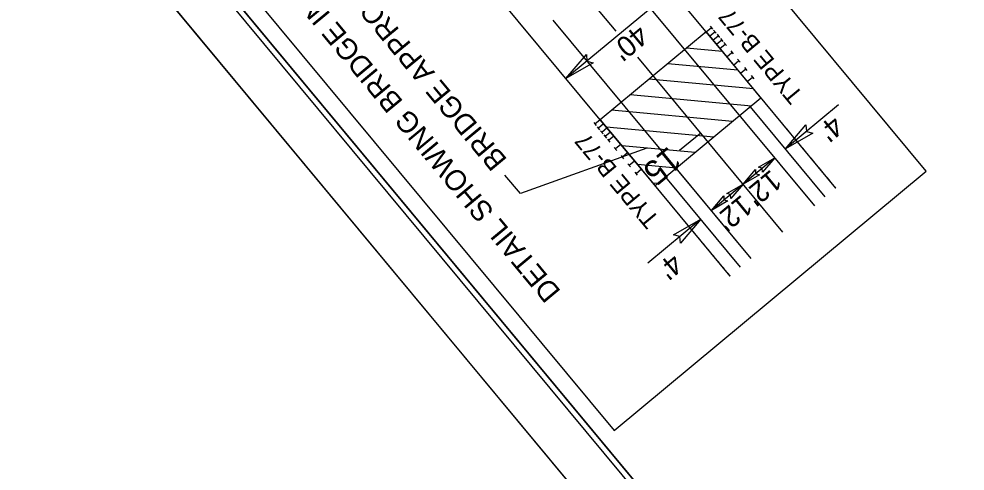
# Model space of a CAD drawing. Extents: x 2597026 to 2598995, y 852197 to 854192.
# Drawn here: x 2597490.1 to 2597902.9, y 852711.2 to 852908.6 of the extents above; entities that cross this region are included whole.
import ezdxf

# ---------------------------------------------------------------- set-up
doc = ezdxf.new("R2010")
doc.units = 0
for name, color, linetype in [('Old_Level_1', 7, 'Continuous'), ('Old_Level_2', 7, 'Continuous'), ('Prop Approach Slab', 7, 'Continuous'), ('Prop Dimension', 7, 'Continuous'), ('Prop Dimension Text', 7, 'Continuous'), ('Prop EOT', 7, 'Continuous'), ('Prop Guardrail', 7, 'Continuous'), ('Prop Horizontal Alignment', 7, 'Continuous'), ('Prop Horizontal Alignment Tick Label', 7, 'Continuous'), ('Prop Horizontal Alignment Tick Large', 7, 'Continuous'), ('Prop Paved Shoulder', 7, 'Continuous'), ('Prop Roadway Bridge', 7, 'Continuous'), ('Prop Structure Anchor Unit CELL', 7, 'Continuous'), ('Prop Terminator CELL', 7, 'Continuous'), ('Sheet Clip Boundary CELL', 7, 'Continuous'), ('Sheet Cutting Line CELL', 7, 'Continuous'), ('Sheet Plan CELL', 7, 'Continuous'), ('Sheet Plan Layout CELL', 7, 'Continuous'), ('Sheet Plot Border Inside CELL', 7, 'Continuous'), ('Sheet Plot Border Outside CELL', 7, 'Continuous')]:
    doc.layers.add(name, color=color, linetype=linetype)

msp = doc.modelspace()

# ---------------------------------------------------------------- linework, layer by layer
at = {"layer": 'Old_Level_1'}
for p, q in [((2597507.53, 853020.63), (2597749.73, 852728.97)), ((2597763.98, 852852.17), (2597708.85, 852832.31)), ((2597749.73, 852728.97), (2597885.92, 852842.07)), ((2597708.85, 852832.31), (2597702.12, 852840.42))]:
    msp.add_line(p, q, dxfattribs=at)
msp.add_lwpolyline([(2597885.92, 852842.07), (2597643.72, 853133.73), (2597507.53, 853020.63)], dxfattribs=at)
at = {"layer": 'Old_Level_2'}
for p, q in [((2597846.51, 852834.7), (2597807.87, 852881.24)), ((2597800.33, 852796.35), (2597761.65, 852842.92))]:
    msp.add_line(p, q, dxfattribs=at)
at = {"layer": 'Prop Approach Slab'}
for p, q in [((2597789.88, 852902.87), (2597813.82, 852874)), ((2597796.98, 852894.31), (2597781.31, 852895.76)), ((2597803.75, 852886.15), (2597773.14, 852888.98)), ((2597810.51, 852877.99), (2597764.97, 852882.21)), ((2597809.64, 852870.54), (2597756.79, 852875.43)), ((2597813.82, 852874), (2597767.63, 852835.7)), ((2597801.47, 852863.76), (2597748.62, 852868.66)), ((2597743.69, 852864.57), (2597767.63, 852835.7)), ((2597793.3, 852856.99), (2597746.38, 852861.34)), ((2597785.13, 852850.21), (2597753.14, 852853.18)), ((2597776.96, 852843.44), (2597759.91, 852845.02)), ((2597768.79, 852836.66), (2597766.67, 852836.86))]:
    msp.add_line(p, q, dxfattribs=at)
at = {"layer": 'Prop Dimension'}
for p, q in [((2597774.92, 852920.89), (2597728.76, 852882.56)), ((2597847.6, 852871.01), (2597824.52, 852851.84)), ((2597819.83, 852847.94), (2597806.02, 852836.48)), ((2597806.02, 852836.48), (2597792.21, 852825.01)), ((2597787.6, 852821.18), (2597764.52, 852802.01))]:
    msp.add_line(p, q, dxfattribs=at)
at = {"layer": 'Prop EOT'}
for p, q in [((2597837.27, 852827.03), (2597751.13, 852930.75)), ((2597809.57, 852804.03), (2597723.22, 852908.01)), ((2597809.57, 852804.03), (2597776.89, 852843.39))]:
    msp.add_line(p, q, dxfattribs=at)
at = {"layer": 'Prop Guardrail'}
for p, q in [((2597807.87, 852881.25), (2597789.88, 852902.87)), ((2597761.68, 852842.95), (2597743.69, 852864.57))]:
    msp.add_line(p, q, dxfattribs=at)
for points in [[(2597846.51, 852834.7), (2597846.38, 852834.86), (2597846.25, 852835.03), (2597846.11, 852835.19), (2597845.81, 852835.55), (2597845.5, 852835.92), (2597845.2, 852836.28), (2597844.9, 852836.65), (2597844.59, 852837.01), (2597844.29, 852837.38), (2597843.99, 852837.75), (2597843.68, 852838.11), (2597843.38, 852838.48), (2597843.08, 852838.84), (2597842.77, 852839.21), (2597842.47, 852839.57), (2597842.17, 852839.94), (2597841.86, 852840.3), (2597841.56, 852840.67), (2597841.26, 852841.03), (2597840.95, 852841.4), (2597840.65, 852841.77), (2597840.34, 852842.13), (2597840.04, 852842.5), (2597839.74, 852842.86), (2597839.43, 852843.23), (2597839.13, 852843.59), (2597838.83, 852843.96), (2597838.52, 852844.32), (2597838.22, 852844.69), (2597837.92, 852845.06), (2597837.61, 852845.42), (2597837.31, 852845.79), (2597837.01, 852846.15), (2597836.7, 852846.52), (2597836.4, 852846.88), (2597836.1, 852847.25), (2597835.79, 852847.61), (2597835.49, 852847.98), (2597835.19, 852848.35), (2597834.88, 852848.71), (2597834.58, 852849.08), (2597834.28, 852849.44), (2597833.97, 852849.81), (2597833.67, 852850.17), (2597833.36, 852850.54), (2597833.06, 852850.9), (2597832.76, 852851.27), (2597832.45, 852851.63), (2597832.15, 852852), (2597831.85, 852852.37), (2597831.54, 852852.73), (2597831.24, 852853.1), (2597830.94, 852853.46), (2597830.63, 852853.83), (2597830.33, 852854.19), (2597830.03, 852854.56), (2597829.72, 852854.92), (2597829.42, 852855.29), (2597829.12, 852855.66), (2597828.81, 852856.02), (2597828.51, 852856.39), (2597828.21, 852856.75), (2597827.9, 852857.12), (2597827.6, 852857.48), (2597827.29, 852857.85), (2597826.99, 852858.21), (2597826.69, 852858.58), (2597826.38, 852858.94), (2597826.08, 852859.31), (2597825.78, 852859.68), (2597825.47, 852860.04), (2597825.17, 852860.41), (2597824.87, 852860.77), (2597824.56, 852861.14), (2597824.26, 852861.5), (2597823.96, 852861.87), (2597823.65, 852862.23), (2597823.35, 852862.6), (2597823.05, 852862.97), (2597822.74, 852863.33), (2597822.44, 852863.7), (2597822.14, 852864.06), (2597821.83, 852864.43), (2597821.53, 852864.79), (2597821.22, 852865.16), (2597820.92, 852865.52), (2597820.62, 852865.89), (2597820.31, 852866.26), (2597820.01, 852866.62), (2597819.71, 852866.99), (2597819.4, 852867.35), (2597819.1, 852867.72), (2597818.8, 852868.08), (2597818.49, 852868.45), (2597818.19, 852868.81), (2597817.89, 852869.18), (2597817.58, 852869.54), (2597817.28, 852869.91), (2597816.98, 852870.28), (2597816.67, 852870.64), (2597816.37, 852871.01), (2597816.07, 852871.37), (2597815.76, 852871.74), (2597815.46, 852872.1), (2597815.16, 852872.47), (2597814.85, 852872.83), (2597814.55, 852873.2), (2597814.24, 852873.57), (2597813.94, 852873.93), (2597813.64, 852874.3), (2597813.33, 852874.66), (2597813.03, 852875.03), (2597812.73, 852875.39), (2597812.42, 852875.76), (2597812.12, 852876.12), (2597811.82, 852876.49), (2597811.51, 852876.85), (2597811.21, 852877.22), (2597810.91, 852877.59), (2597810.6, 852877.95), (2597810.3, 852878.32), (2597810, 852878.68), (2597809.69, 852879.05), (2597809.39, 852879.41), (2597809.09, 852879.78), (2597808.78, 852880.14), (2597808.48, 852880.51), (2597808.17, 852880.88), (2597807.87, 852881.24)], [(2597761.65, 852842.92), (2597761.91, 852842.61), (2597762.16, 852842.3), (2597762.42, 852841.99), (2597762.68, 852841.68), (2597762.93, 852841.37), (2597763.19, 852841.06), (2597763.44, 852840.76), (2597763.7, 852840.45), (2597763.96, 852840.14), (2597764.21, 852839.83), (2597764.47, 852839.52), (2597764.73, 852839.21), (2597764.98, 852838.9), (2597765.24, 852838.6), (2597765.49, 852838.29), (2597765.75, 852837.98), (2597766.01, 852837.67), (2597766.26, 852837.36), (2597766.52, 852837.05), (2597766.78, 852836.74), (2597767.03, 852836.44), (2597767.29, 852836.13), (2597767.55, 852835.82), (2597767.8, 852835.51), (2597768.06, 852835.2), (2597768.31, 852834.89), (2597768.57, 852834.58), (2597768.83, 852834.28), (2597769.08, 852833.97), (2597769.34, 852833.66), (2597769.6, 852833.35), (2597769.85, 852833.04), (2597770.11, 852832.73), (2597770.37, 852832.42), (2597770.62, 852832.12), (2597770.88, 852831.81), (2597771.13, 852831.5), (2597771.39, 852831.19), (2597771.65, 852830.88), (2597771.9, 852830.57), (2597772.16, 852830.26), (2597772.42, 852829.95), (2597772.67, 852829.65), (2597772.93, 852829.34), (2597773.18, 852829.03), (2597773.44, 852828.72), (2597773.7, 852828.41), (2597773.95, 852828.1), (2597774.21, 852827.79), (2597774.47, 852827.49), (2597774.72, 852827.18), (2597774.98, 852826.87), (2597775.24, 852826.56), (2597775.49, 852826.25), (2597775.75, 852825.94), (2597776, 852825.63), (2597776.26, 852825.33), (2597776.52, 852825.02), (2597776.77, 852824.71), (2597777.03, 852824.4), (2597777.29, 852824.09), (2597777.54, 852823.78), (2597777.8, 852823.47), (2597778.06, 852823.17), (2597778.31, 852822.86), (2597778.57, 852822.55), (2597778.82, 852822.24), (2597779.08, 852821.93), (2597779.34, 852821.62), (2597779.59, 852821.31), (2597779.85, 852821.01), (2597780.11, 852820.7), (2597780.36, 852820.39), (2597780.62, 852820.08), (2597780.87, 852819.77), (2597781.13, 852819.46), (2597781.39, 852819.15), (2597781.64, 852818.85), (2597781.9, 852818.54), (2597782.16, 852818.23), (2597782.41, 852817.92), (2597782.67, 852817.61), (2597782.93, 852817.3), (2597783.18, 852816.99), (2597783.44, 852816.68), (2597783.69, 852816.38), (2597783.95, 852816.07), (2597784.21, 852815.76), (2597784.46, 852815.45), (2597784.72, 852815.14), (2597784.98, 852814.83), (2597785.23, 852814.52), (2597785.49, 852814.22), (2597785.75, 852813.91), (2597786, 852813.6), (2597786.26, 852813.29), (2597786.51, 852812.98), (2597786.77, 852812.67), (2597787.03, 852812.36), (2597787.28, 852812.06), (2597787.54, 852811.75), (2597787.8, 852811.44), (2597788.05, 852811.13), (2597788.31, 852810.82), (2597788.57, 852810.51), (2597788.82, 852810.2), (2597789.08, 852809.9), (2597789.33, 852809.59), (2597789.59, 852809.28), (2597789.85, 852808.97), (2597790.1, 852808.66), (2597790.36, 852808.35), (2597790.62, 852808.04), (2597790.87, 852807.74), (2597791.13, 852807.43), (2597791.38, 852807.12), (2597791.64, 852806.81), (2597791.9, 852806.5), (2597792.15, 852806.19), (2597792.41, 852805.88), (2597792.67, 852805.57), (2597792.92, 852805.27), (2597793.18, 852804.96), (2597793.44, 852804.65), (2597793.69, 852804.34), (2597793.95, 852804.03), (2597794.2, 852803.72), (2597794.46, 852803.41), (2597794.72, 852803.11), (2597794.97, 852802.8), (2597795.23, 852802.49), (2597795.49, 852802.18), (2597795.74, 852801.87), (2597796, 852801.56), (2597796.26, 852801.25), (2597796.51, 852800.95), (2597796.77, 852800.64), (2597797.02, 852800.33), (2597797.28, 852800.02), (2597797.54, 852799.71), (2597797.79, 852799.4), (2597798.05, 852799.09), (2597798.31, 852798.79), (2597798.56, 852798.48), (2597798.82, 852798.17), (2597799.07, 852797.86), (2597799.33, 852797.55), (2597799.59, 852797.24), (2597799.84, 852796.93), (2597800.1, 852796.63), (2597800.18, 852796.53), (2597800.25, 852796.44), (2597800.33, 852796.35)]]:
    msp.add_open_spline(points, degree=3, dxfattribs=at)
at = {"layer": 'Prop Horizontal Alignment'}
for p, q in [((2597750.61, 852903.2), (2597702.87, 852960.69)), ((2597823.42, 852815.53), (2597760.03, 852891.86))]:
    msp.add_line(p, q, dxfattribs=at)
at = {"layer": 'Prop Horizontal Alignment Tick Large'}
msp.add_line((2597787.53, 852858.75), (2597778.29, 852851.08), dxfattribs=at)
at = {"layer": 'Prop Paved Shoulder'}
for p, q in [((2597841.88, 852830.86), (2597809.22, 852870.19)), ((2597804.95, 852800.19), (2597772.27, 852839.55))]:
    msp.add_line(p, q, dxfattribs=at)
at = {"layer": 'Prop Roadway Bridge'}
for p, q in [((2597789.88, 852902.87), (2597703.64, 853006.73)), ((2597743.69, 852864.57), (2597657.45, 852968.43)), ((2597789.88, 852902.87), (2597743.69, 852864.57)), ((2597790.22, 852902.47), (2597789.48, 852902.54))]:
    msp.add_line(p, q, dxfattribs=at)
at = {"layer": 'Prop Structure Anchor Unit CELL'}
for p, q in [((2597789.88, 852902.87), (2597792.19, 852904.78)), ((2597789.88, 852902.87), (2597807.83, 852881.22)), ((2597791.38, 852901.06), (2597793.69, 852902.98)), ((2597791.64, 852905.45), (2597792.74, 852904.12)), ((2597793.14, 852903.64), (2597794.24, 852902.32)), ((2597792.87, 852899.26), (2597795.18, 852901.18)), ((2597794.37, 852897.46), (2597796.68, 852899.37)), ((2597794.64, 852901.84), (2597795.73, 852900.51)), ((2597796.13, 852900.03), (2597797.23, 852898.71)), ((2597797.63, 852898.23), (2597798.72, 852896.91)), ((2597795.87, 852895.65), (2597798.18, 852897.57)), ((2597800.62, 852894.62), (2597801.72, 852893.3)), ((2597798.86, 852892.04), (2597801.17, 852893.96)), ((2597801.85, 852888.43), (2597804.16, 852890.35)), ((2597803.61, 852891.01), (2597804.71, 852889.69)), ((2597804.84, 852884.83), (2597807.15, 852886.74)), ((2597806.6, 852887.4), (2597807.7, 852886.08)), ((2597807.83, 852881.22), (2597810.14, 852883.13)), ((2597809.6, 852883.79), (2597810.69, 852882.47)), ((2597740.84, 852863.32), (2597741.93, 852862)), ((2597743.69, 852864.57), (2597741.38, 852862.66)), ((2597742.33, 852861.52), (2597743.43, 852860.19)), ((2597745.19, 852862.77), (2597742.88, 852860.85)), ((2597743.69, 852864.57), (2597761.65, 852842.92)), ((2597743.83, 852859.71), (2597744.92, 852858.39)), ((2597746.69, 852860.96), (2597744.38, 852859.05)), ((2597745.32, 852857.91), (2597746.42, 852856.58)), ((2597748.18, 852859.16), (2597745.87, 852857.25)), ((2597749.68, 852857.36), (2597747.37, 852855.44)), ((2597746.82, 852856.1), (2597747.92, 852854.78)), ((2597752.67, 852853.75), (2597750.36, 852851.83)), ((2597749.81, 852852.49), (2597750.91, 852851.17)), ((2597752.8, 852848.89), (2597753.9, 852847.56)), ((2597755.66, 852850.14), (2597753.35, 852848.22)), ((2597755.8, 852845.28), (2597756.89, 852843.95)), ((2597758.65, 852846.53), (2597756.34, 852844.62)), ((2597758.79, 852841.67), (2597759.88, 852840.35)), ((2597761.65, 852842.92), (2597759.34, 852841.01))]:
    msp.add_line(p, q, dxfattribs=at)
at = {"layer": 'Prop Terminator CELL'}
for points in [[(2597740.63, 852889.39), (2597728.76, 852882.56), (2597737.67, 852893.08), (2597737.88, 852890.13)], [(2597836.39, 852858.68), (2597824.52, 852851.84), (2597833.43, 852862.36), (2597833.64, 852859.41)], [(2597812.75, 852843.88), (2597819.88, 852847.98), (2597814.53, 852841.67), (2597814.41, 852843.44)], [(2597813.14, 852840.58), (2597806.02, 852836.48), (2597811.37, 852842.79), (2597811.49, 852841.02)], [(2597798.9, 852832.38), (2597806.02, 852836.48), (2597800.67, 852830.17), (2597800.55, 852831.93)], [(2597799.33, 852829.11), (2597792.21, 852825.01), (2597797.56, 852831.32), (2597797.68, 852829.55)], [(2597775.72, 852814.34), (2597787.6, 852821.18), (2597778.68, 852810.66), (2597778.48, 852813.61)]]:
    msp.add_lwpolyline(points, close=True, dxfattribs=at)
at = {"layer": 'Sheet Clip Boundary CELL'}
msp.add_lwpolyline([(2598839.68, 853048.61), (2597945.27, 854125.68), (2597300.19, 853589.99), (2597421.1, 853444.38), (2597258.39, 853309.27), (2598031.89, 852377.81)], close=True, dxfattribs=at)
at = {"layer": 'Sheet Cutting Line CELL'}
msp.add_line((2597077.38, 853492.06), (2598152.9, 852196.9), dxfattribs=at)
at = {"layer": 'Sheet Plan CELL'}
for points in [[(2597105.52, 853493.36), (2598063.83, 852339.35), (2598871.63, 853010.15), (2597913.33, 854164.14)], [(2598871.63, 853010.15), (2598063.87, 852339.34), (2597233.33, 853339.43), (2597348.77, 853435.31), (2597220.99, 853589.21), (2597913.33, 854164.14)]]:
    msp.add_lwpolyline(points, close=True, dxfattribs=at)
at = {"layer": 'Sheet Plan Layout CELL'}
msp.add_lwpolyline([(2598063.87, 852339.34), (2598871.63, 853010.15), (2597913.34, 854164.13), (2597268.25, 853628.44), (2597421.1, 853444.38), (2597258.39, 853309.27)], close=True, dxfattribs=at)
at = {"layer": 'Sheet Plot Border Inside CELL'}
msp.add_lwpolyline([(2598971.62, 852893.67), (2597907.28, 854175.35), (2597095.64, 853501.37), (2598159.98, 852219.68)], close=True, dxfattribs=at)
at = {"layer": 'Sheet Plot Border Outside CELL'}
msp.add_lwpolyline([(2598995.31, 852896.45), (2597919.79, 854191.6), (2597077.38, 853492.06), (2598152.9, 852196.9)], close=True, dxfattribs=at)

# ---------------------------------------------------------------- texts
at = {"layer": 'Old_Level_1'}
for s, p in [('DETAIL SHOWING BRIDGE IN RELATION TO PAVEMENT', (2597726.83, 852789.62)), ('BRIDGE APPROACH SLAB', (2597703.44, 852847.12))]:
    msp.add_text(s, height=9, rotation=129.7067, dxfattribs=at).set_placement(p)
at = {"layer": 'Prop Dimension Text'}
for s, p in [("40'", (2597760.08, 852906.59)), ("4'", (2597845.08, 852866.96)), ("12'", (2597818.16, 852843.17)), ("12'", (2597805.38, 852832.18)), ("4'", (2597775.01, 852806.8))]:
    msp.add_text(s, height=9, rotation=219.7067, dxfattribs=at).set_placement(p)
at = {"layer": 'Prop Horizontal Alignment Tick Label'}
msp.add_text('15', height=10.5, rotation=219.7067, dxfattribs=at).set_placement((2597773.54, 852853.32))
at = {"layer": 'Prop Structure Anchor Unit CELL'}
for p in [(2597832.61, 852875.48), (2597769.9, 852821.16)]:
    msp.add_text('TYPE B-77', height=7.5, rotation=129.7067, dxfattribs=at).set_placement(p)

doc.saveas('drawing.dxf')
